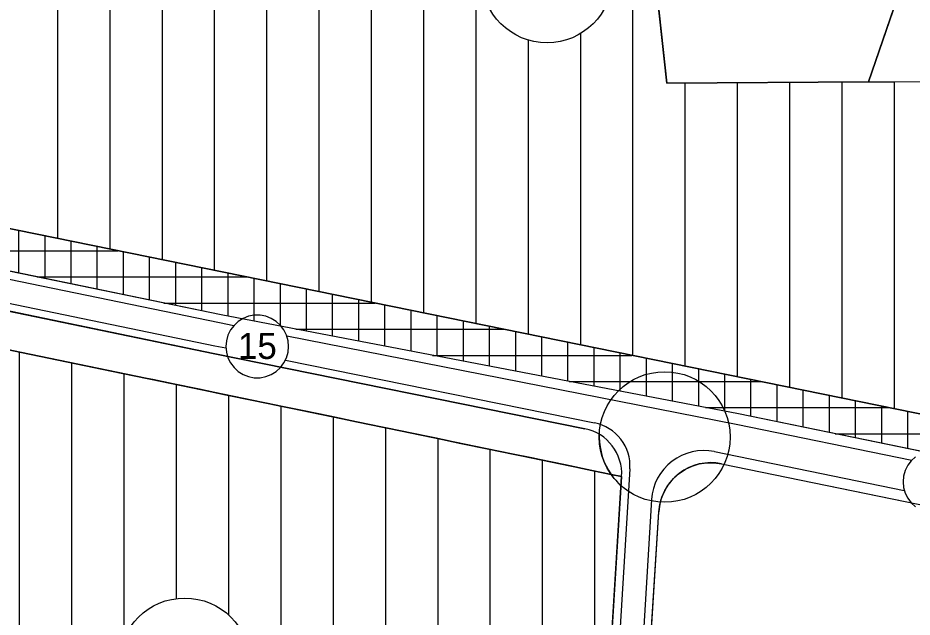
# Model space of a CAD drawing. Extents: x 427903 to 430077, y 4477233 to 4480385.
# Drawn here: x 428977.5 to 429319.5, y 4477464.3 to 4477693.6 of the extents above; entities that cross this region are included whole.
import ezdxf

# ---------------------------------------------------------------- set-up
doc = ezdxf.new("R2010")
doc.units = 0
for name, color, linetype in [('ADA', 7, 'Continuous'), ('ADAKENARI', 7, 'Continuous'), ('KALDIRIM', 7, 'Continuous'), ('KD_DAIRE', 7, 'Continuous'), ('KD_KAV_DA', 7, 'Continuous'), ('KD_YGEN', 7, 'Continuous'), ('PL_K_BHA', 7, 'Continuous'), ('PL_K_TALI_IS_MRK', 7, 'Continuous'), ('PL_KON_MEV_150', 7, 'Continuous'), ('PL_SAY_SPOR', 7, 'Continuous'), ('SM_DAIRE', 7, 'Continuous'), ('TR_AZYOGUNKONUT', 7, 'Continuous'), ('TR_TALIISMERK', 7, 'Continuous')]:
    doc.layers.add(name, color=color, linetype=linetype)

msp = doc.modelspace()

# ---------------------------------------------------------------- linework, layer by layer
at = {"layer": 'ADA'}
for p, q in [((429217.51, 4477743.44), (429225.77, 4477668.67)), ((429302.83, 4477669.13), (429323.01, 4477727.85)), ((429225.77, 4477668.67), (429302.83, 4477669.13)), ((429302.83, 4477669.13), (429349.51, 4477669.41))]:
    msp.add_line(p, q, dxfattribs=at)
at = {"layer": 'ADAKENARI'}
for p, q in [((429528.47, 4477500.12), (428912.77, 4477625.48)), ((429055.28, 4477579.93), (428907.79, 4477610.43)), ((428924.99, 4477591.56), (429052.27, 4477565.24)), ((429253.08, 4477542.08), (429055.28, 4477579.93)), ((428978.93, 4477565.57), (429208.41, 4477518.08)), ((429052.27, 4477565.24), (429194.39, 4477536.36)), ((429530.08, 4477485.18), (429253.08, 4477542.08)), ((429246.63, 4477522.99), (429411.9, 4477489.04)), ((429208.41, 4477518.08), (429198.53, 4477358.41)), ((429213.49, 4477357.28), (429222.61, 4477504.61))]:
    msp.add_line(p, q, dxfattribs=at)
for centre, radius, start, end in [((429190.9, 4477519.16), 17.55, 356.4594, 78.5144), ((429242.6, 4477503.38), 20.03, 78.3918, 176.4594)]:
    msp.add_arc(centre, radius, start, end, dxfattribs=at)
at = {"layer": 'KALDIRIM'}
for p, q in [((428907.19, 4477607.49), (429054.67, 4477577)), ((428925.59, 4477594.5), (429052.87, 4477568.18)), ((429054.67, 4477577), (429060.15, 4477575.92)), ((429080.33, 4477571.95), (429252.27, 4477538.17)), ((429052.87, 4477568.18), (429057.06, 4477567.33)), ((429079.88, 4477562.69), (429198.02, 4477538.69)), ((429252.27, 4477538.17), (429319.4, 4477524.38)), ((429243.88, 4477527.64), (429316.54, 4477512.72)), ((429211.6, 4477520.98), (429206.63, 4477440.76)), ((429219.89, 4477509.29), (429215.61, 4477440.13))]:
    msp.add_line(p, q, dxfattribs=at)
for centre, radius, start, end in [((429194.63, 4477522.03), 17, 356.4594, 78.5144), ((429239.85, 4477508.05), 20, 78.3918, 176.4594)]:
    msp.add_arc(centre, radius, start, end, dxfattribs=at)
at = {"layer": 'KD_DAIRE'}
for p, q in [((429063.7, 4477578.61), (429061.82, 4477577.44)), ((429063.7, 4477578.61), (429061.82, 4477577.44)), ((429065.77, 4477579.41), (429063.7, 4477578.61)), ((429065.77, 4477579.41), (429063.7, 4477578.61)), ((429067.94, 4477579.82), (429065.77, 4477579.41)), ((429067.94, 4477579.82), (429065.77, 4477579.41)), ((429070.16, 4477579.82), (429067.94, 4477579.82)), ((429070.16, 4477579.82), (429067.94, 4477579.82)), ((429072.33, 4477579.41), (429070.16, 4477579.82)), ((429072.33, 4477579.41), (429070.16, 4477579.82)), ((429074.4, 4477578.61), (429072.33, 4477579.41)), ((429074.4, 4477578.61), (429072.33, 4477579.41)), ((429076.28, 4477577.44), (429074.4, 4477578.61)), ((429076.28, 4477577.44), (429074.4, 4477578.61)), ((429060.18, 4477575.95), (429058.85, 4477574.19)), ((429060.18, 4477575.95), (429058.85, 4477574.19)), ((429061.82, 4477577.44), (429060.18, 4477575.95)), ((429061.82, 4477577.44), (429060.18, 4477575.95)), ((429077.92, 4477575.95), (429076.28, 4477577.44)), ((429077.92, 4477575.95), (429076.28, 4477577.44)), ((429079.25, 4477574.19), (429077.92, 4477575.95)), ((429079.25, 4477574.19), (429077.92, 4477575.95)), ((429057.86, 4477572.2), (429057.25, 4477570.07)), ((429057.86, 4477572.2), (429057.25, 4477570.07)), ((429058.85, 4477574.19), (429057.86, 4477572.2)), ((429058.85, 4477574.19), (429057.86, 4477572.2)), ((429080.24, 4477572.2), (429079.25, 4477574.19)), ((429080.24, 4477572.2), (429079.25, 4477574.19)), ((429080.84, 4477570.07), (429080.24, 4477572.2)), ((429080.84, 4477570.07), (429080.24, 4477572.2)), ((429057.25, 4477570.07), (429057.05, 4477567.87)), ((429057.25, 4477570.07), (429057.05, 4477567.87)), ((429081.05, 4477567.87), (429080.84, 4477570.07)), ((429081.05, 4477567.87), (429080.84, 4477570.07)), ((429057.05, 4477567.87), (429057.25, 4477565.66)), ((429057.05, 4477567.87), (429057.25, 4477565.66)), ((429057.25, 4477565.66), (429057.86, 4477563.53)), ((429057.25, 4477565.66), (429057.86, 4477563.53)), ((429080.24, 4477563.53), (429080.84, 4477565.66)), ((429080.24, 4477563.53), (429080.84, 4477565.66)), ((429080.84, 4477565.66), (429081.05, 4477567.87)), ((429080.84, 4477565.66), (429081.05, 4477567.87)), ((429081.05, 4477567.87), (429081.05, 4477567.87)), ((429081.05, 4477567.87), (429081.05, 4477567.87)), ((429057.86, 4477563.53), (429058.85, 4477561.55)), ((429057.86, 4477563.53), (429058.85, 4477561.55)), ((429058.85, 4477561.55), (429060.18, 4477559.78)), ((429058.85, 4477561.55), (429060.18, 4477559.78)), ((429077.92, 4477559.78), (429079.25, 4477561.55)), ((429077.92, 4477559.78), (429079.25, 4477561.55)), ((429079.25, 4477561.55), (429080.24, 4477563.53)), ((429079.25, 4477561.55), (429080.24, 4477563.53)), ((429060.18, 4477559.78), (429061.82, 4477558.29)), ((429060.18, 4477559.78), (429061.82, 4477558.29)), ((429061.82, 4477558.29), (429063.7, 4477557.13)), ((429061.82, 4477558.29), (429063.7, 4477557.13)), ((429074.4, 4477557.13), (429076.28, 4477558.29)), ((429074.4, 4477557.13), (429076.28, 4477558.29)), ((429076.28, 4477558.29), (429077.92, 4477559.78)), ((429076.28, 4477558.29), (429077.92, 4477559.78)), ((429063.7, 4477557.13), (429065.77, 4477556.33)), ((429063.7, 4477557.13), (429065.77, 4477556.33)), ((429065.77, 4477556.33), (429067.94, 4477555.92)), ((429065.77, 4477556.33), (429067.94, 4477555.92)), ((429067.94, 4477555.92), (429070.16, 4477555.92)), ((429067.94, 4477555.92), (429070.16, 4477555.92)), ((429070.16, 4477555.92), (429072.33, 4477556.33)), ((429070.16, 4477555.92), (429072.33, 4477556.33)), ((429072.33, 4477556.33), (429074.4, 4477557.13)), ((429072.33, 4477556.33), (429074.4, 4477557.13)), ((429319.19, 4477524.15), (429317.86, 4477522.38)), ((429319.19, 4477524.15), (429317.86, 4477522.38)), ((429320.83, 4477525.64), (429319.19, 4477524.15)), ((429320.83, 4477525.64), (429319.19, 4477524.15)), ((429316.87, 4477520.4), (429316.26, 4477518.27)), ((429316.87, 4477520.4), (429316.26, 4477518.27)), ((429317.86, 4477522.38), (429316.87, 4477520.4)), ((429317.86, 4477522.38), (429316.87, 4477520.4)), ((429316.26, 4477518.27), (429316.06, 4477516.06)), ((429316.26, 4477518.27), (429316.06, 4477516.06)), ((429316.06, 4477516.06), (429316.26, 4477513.86)), ((429316.06, 4477516.06), (429316.26, 4477513.86)), ((429316.26, 4477513.86), (429316.87, 4477511.73)), ((429316.26, 4477513.86), (429316.87, 4477511.73)), ((429316.87, 4477511.73), (429317.86, 4477509.75)), ((429316.87, 4477511.73), (429317.86, 4477509.75)), ((429317.86, 4477509.75), (429319.19, 4477507.98)), ((429317.86, 4477509.75), (429319.19, 4477507.98)), ((429319.19, 4477507.98), (429320.83, 4477506.49)), ((429319.19, 4477507.98), (429320.83, 4477506.49))]:
    msp.add_line(p, q, dxfattribs=at)
at = {"layer": 'KD_KAV_DA'}
msp.add_circle((429224.89, 4477533.22), 25, dxfattribs=at)
at = {"layer": 'PL_K_BHA'}
msp.add_lwpolyline([(429325.91, 4477853.36), (429323.01, 4477727.85), (429302.83, 4477669.13), (429225.77, 4477668.67), (429217.51, 4477743.44), (429182.19, 4477742.53), (429185.4, 4477776.47), (429130.82, 4477785.19), (429146.75, 4477845.66), (429150.95, 4477861.61), (429260.07, 4477868.35), (429268.61, 4477868.97), (429281.61, 4477869.09), (429292.6, 4477869.49), (429326.26, 4477868.29)], close=True, dxfattribs=at)
at = {"layer": 'PL_K_TALI_IS_MRK'}
for points in [[(428912.77, 4477625.48), (429528.47, 4477500.12)], [(429530.08, 4477485.18), (429253.08, 4477542.08), (429055.28, 4477579.93), (428907.79, 4477610.43)], [(429194.39, 4477536.36), (429052.27, 4477565.24), (428945.43, 4477587.33), (428942.16, 4477573.18), (428978.93, 4477565.57), (429016.97, 4477557.7)], [(429016.97, 4477557.7), (429026.97, 4477555.63), (429029.11, 4477555.19), (429036.97, 4477553.56), (429046.97, 4477551.49), (429056.97, 4477549.42), (429066.97, 4477547.35), (429076.97, 4477545.28), (429077.42, 4477545.19), (429086.97, 4477543.21), (429096.97, 4477541.14), (429106.97, 4477539.07), (429116.97, 4477537), (429125.74, 4477535.19), (429126.97, 4477534.93), (429136.97, 4477532.86), (429146.97, 4477530.79), (429156.97, 4477528.73), (429166.97, 4477526.66), (429174.06, 4477525.19), (429176.97, 4477524.59), (429186.97, 4477522.52), (429196.97, 4477520.45), (429204.39, 4477518.91), (429208.41, 4477518.08)]]:
    msp.add_lwpolyline(points, dxfattribs=at)
msp.add_arc((429190.9, 4477519.16), 17.55, 356.4594, 78.5144, dxfattribs=at)
at = {"layer": 'PL_KON_MEV_150'}
msp.add_lwpolyline([(429217.51, 4477743.44), (429225.77, 4477668.67), (429302.83, 4477669.13), (429349.51, 4477669.41), (429349.16, 4477727.85), (429323.01, 4477727.85), (429325.91, 4477853.36), (429488.36, 4477840.99), (429552.87, 4477514.62), (429528.47, 4477500.12), (428912.77, 4477625.48), (428938.14, 4477835.78), (429146.75, 4477845.66), (429130.82, 4477785.19), (429185.4, 4477776.47), (429182.19, 4477742.53)], close=True, dxfattribs=at)
msp.add_lwpolyline([(429198.53, 4477358.41), (429208.41, 4477518.08), (429204.39, 4477518.91), (429196.97, 4477520.45), (429186.97, 4477522.52), (429176.97, 4477524.59), (429174.06, 4477525.19), (429166.97, 4477526.66), (429156.97, 4477528.73), (429146.97, 4477530.79), (429136.97, 4477532.86), (429126.97, 4477534.93), (429125.74, 4477535.19), (429116.97, 4477537), (429106.97, 4477539.07), (429096.97, 4477541.14), (429086.97, 4477543.21), (429077.42, 4477545.19), (429076.97, 4477545.28), (429066.97, 4477547.35), (429056.97, 4477549.42), (429046.97, 4477551.49), (429036.97, 4477553.56), (429029.11, 4477555.19), (429026.97, 4477555.63), (429016.97, 4477557.7), (428978.93, 4477565.57), (428942.16, 4477573.18)], dxfattribs=at)
at = {"layer": 'PL_SAY_SPOR'}
for points in [[(429332.77, 4477669.31), (429349.51, 4477669.41), (429349.16, 4477727.85), (429332.77, 4477727.85), (429323.01, 4477727.85), (429302.83, 4477669.13), (429312.77, 4477669.19), (429332.77, 4477669.31)], [(429325.84, 4477331.6), (429212.33, 4477344.27), (429213.49, 4477357.28), (429222.61, 4477504.61), (429222.99, 4477507.44), (429223.76, 4477510.19), (429224.92, 4477512.8), (429226.44, 4477515.21), (429228.29, 4477517.39), (429230.43, 4477519.28), (429232.81, 4477520.85), (429235.39, 4477522.06), (429238.12, 4477522.9), (429240.94, 4477523.33), (429243.8, 4477523.37), (429246.63, 4477522.99), (429411.9, 4477489.04)]]:
    msp.add_lwpolyline(points, dxfattribs=at)
at = {"layer": 'SM_DAIRE'}
for centre in [(429179.89, 4477709.1), (429041.35, 4477446.59)]:
    msp.add_circle(centre, 25, dxfattribs=at)
at = {"layer": 'TR_AZYOGUNKONUT'}
for p, q in [((429072.77, 4477592.9), (429072.77, 4477842.16)), ((429092.77, 4477588.83), (429092.77, 4477843.1)), ((429112.77, 4477584.76), (429112.77, 4477844.05)), ((428992.77, 4477609.19), (428992.77, 4477838.37)), ((429012.77, 4477605.12), (429012.77, 4477839.31)), ((429032.77, 4477601.05), (429032.77, 4477840.26)), ((429052.77, 4477596.97), (429052.77, 4477841.21)), ((429132.77, 4477580.69), (429132.77, 4477784.87)), ((429152.77, 4477576.61), (429152.77, 4477781.68)), ((429212.77, 4477564.4), (429212.77, 4477743.32)), ((429172.77, 4477572.54), (429172.77, 4477685.13)), ((429192.77, 4477568.47), (429192.77, 4477687.67)), ((429232.77, 4477560.33), (429232.77, 4477668.72)), ((429252.77, 4477556.25), (429252.77, 4477668.83)), ((429272.77, 4477552.18), (429272.77, 4477668.95)), ((429292.77, 4477548.11), (429292.77, 4477669.07)), ((429312.77, 4477544.04), (429312.77, 4477669.19)), ((428978.2, 4477461.06), (428978.2, 4477565.72)), ((428998.2, 4477347.08), (428998.2, 4477561.58)), ((429018.2, 4477456.05), (429018.2, 4477557.44)), ((429038.2, 4477471.4), (429038.2, 4477553.31)), ((429058.2, 4477465.06), (429058.2, 4477549.17)), ((429078.2, 4477339.77), (429078.2, 4477545.03)), ((429098.2, 4477337.94), (429098.2, 4477540.89)), ((429118.2, 4477336.11), (429118.2, 4477536.75)), ((429138.2, 4477334.28), (429138.2, 4477532.61)), ((429158.2, 4477464.4), (429158.2, 4477528.47)), ((429178.2, 4477460.93), (429178.2, 4477524.33)), ((429198.2, 4477457.45), (429198.2, 4477520.19)), ((429158.2, 4477332.45), (429158.2, 4477464.4))]:
    msp.add_line(p, q, dxfattribs=at)
for points in [[(429204.39, 4477518.91), (428978.93, 4477565.57), (428942.16, 4477573.18), (428939.78, 4477562.84), (428951.55, 4477560.51), (428949.08, 4477551.4), (428944.47, 4477534.41), (428920.67, 4477537.5), (428893.84, 4477540.99), (428893.57, 4477524.11), (428892.66, 4477466.82)], [(429204.39, 4477518.91), (429196.97, 4477520.45), (429186.97, 4477522.52), (429176.97, 4477524.59), (429174.06, 4477525.19), (429166.97, 4477526.66), (429156.97, 4477528.73), (429146.97, 4477530.79), (429136.97, 4477532.86), (429126.97, 4477534.93), (429125.74, 4477535.19), (429116.97, 4477537), (429106.97, 4477539.07), (429096.97, 4477541.14), (429086.97, 4477543.21), (429077.42, 4477545.19), (429076.97, 4477545.28), (429066.97, 4477547.35), (429056.97, 4477549.42), (429046.97, 4477551.49), (429036.97, 4477553.56), (429029.11, 4477555.19), (429026.97, 4477555.63), (429016.97, 4477557.7), (428978.93, 4477565.57)], [(429204.39, 4477518.91), (429196.97, 4477520.45), (429186.97, 4477522.52), (429176.97, 4477524.59), (429174.06, 4477525.19), (429166.97, 4477526.66), (429156.97, 4477528.73), (429146.97, 4477530.79), (429136.97, 4477532.86), (429126.97, 4477534.93), (429125.74, 4477535.19), (429116.97, 4477537), (429106.97, 4477539.07), (429096.97, 4477541.14), (429086.97, 4477543.21), (429077.42, 4477545.19), (429076.97, 4477545.28), (429066.97, 4477547.35), (429056.97, 4477549.42), (429046.97, 4477551.49), (429036.97, 4477553.56), (429029.11, 4477555.19), (429026.97, 4477555.63), (429016.97, 4477557.7)], [(429203.53, 4477439.18), (429208.2, 4477514.61)]]:
    msp.add_lwpolyline(points, dxfattribs=at)
for start, end in [(177.82, 180), (180, 214.9214), (214.9214, 228.1118), (214.9214, 228.1118), (214.9214, 228.1118)]:
    msp.add_arc((429224.89, 4477533.22), 25, start, end, dxfattribs=at)
at = {"layer": 'TR_TALIISMERK'}
for p, q in [((428977.9, 4477595.93), (428977.9, 4477612.22)), ((428987.9, 4477593.87), (428987.9, 4477610.18)), ((428997.9, 4477591.8), (428997.9, 4477608.15)), ((429007.9, 4477589.73), (429007.9, 4477606.11)), ((428936.58, 4477604.48), (429015.91, 4477604.48)), ((429017.9, 4477587.66), (429017.9, 4477604.07)), ((429027.9, 4477585.59), (429027.9, 4477602.04)), ((429037.9, 4477583.53), (429037.9, 4477600)), ((429047.9, 4477581.46), (429047.9, 4477597.97)), ((429057.9, 4477579.43), (429057.9, 4477595.93)), ((428984.93, 4477594.48), (429065.02, 4477594.48)), ((429067.9, 4477577.52), (429067.9, 4477593.89)), ((429077.9, 4477575.6), (429077.9, 4477591.86)), ((429087.9, 4477573.69), (429087.9, 4477589.82)), ((429097.9, 4477571.78), (429097.9, 4477587.79)), ((429107.9, 4477569.86), (429107.9, 4477585.75)), ((429033.29, 4477584.48), (429114.14, 4477584.48)), ((429117.9, 4477567.95), (429117.9, 4477583.71)), ((429127.9, 4477566.04), (429127.9, 4477581.68)), ((429137.9, 4477564.12), (429137.9, 4477579.64)), ((429147.9, 4477562.21), (429147.9, 4477577.61)), ((429157.9, 4477560.3), (429157.9, 4477575.57)), ((429083.78, 4477574.48), (429163.25, 4477574.48)), ((429167.9, 4477558.38), (429167.9, 4477573.53)), ((429177.9, 4477556.47), (429177.9, 4477571.5)), ((429187.9, 4477554.56), (429187.9, 4477569.46)), ((429197.9, 4477552.64), (429197.9, 4477567.42)), ((429207.9, 4477550.73), (429207.9, 4477565.39)), ((429136.04, 4477564.48), (429212.37, 4477564.48)), ((429217.9, 4477548.81), (429217.9, 4477563.35)), ((429227.9, 4477546.9), (429227.9, 4477561.32)), ((429237.9, 4477544.99), (429237.9, 4477559.28)), ((429188.3, 4477554.48), (429261.48, 4477554.48)), ((429247.9, 4477543.07), (429247.9, 4477557.24)), ((429257.9, 4477541.09), (429257.9, 4477555.21)), ((429267.9, 4477539.04), (429267.9, 4477553.17)), ((429277.9, 4477536.98), (429277.9, 4477551.14)), ((429287.9, 4477534.93), (429287.9, 4477549.1)), ((429240.56, 4477544.48), (429310.6, 4477544.48)), ((429297.9, 4477532.88), (429297.9, 4477547.06)), ((429307.9, 4477530.82), (429307.9, 4477545.03)), ((429317.9, 4477528.77), (429317.9, 4477542.99)), ((429290.09, 4477534.48), (429359.71, 4477534.48))]:
    msp.add_line(p, q, dxfattribs=at)
for points in [[(429194.39, 4477536.36), (429052.27, 4477565.24), (428945.43, 4477587.33), (428942.16, 4477573.18), (428978.93, 4477565.57), (429016.97, 4477557.7)], [(429016.97, 4477557.7), (429026.97, 4477555.63), (429029.11, 4477555.19), (429036.97, 4477553.56), (429046.97, 4477551.49), (429056.97, 4477549.42), (429066.97, 4477547.35), (429076.97, 4477545.28), (429077.42, 4477545.19), (429086.97, 4477543.21), (429096.97, 4477541.14), (429106.97, 4477539.07), (429116.97, 4477537), (429125.74, 4477535.19), (429126.97, 4477534.93), (429136.97, 4477532.86), (429146.97, 4477530.79), (429156.97, 4477528.73), (429166.97, 4477526.66), (429174.06, 4477525.19), (429176.97, 4477524.59), (429186.97, 4477522.52), (429196.97, 4477520.45), (429204.39, 4477518.91), (429208.41, 4477518.08)]]:
    msp.add_lwpolyline(points, dxfattribs=at)
msp.add_arc((429190.9, 4477519.16), 17.55, 356.4594, 78.5144, dxfattribs=at)

# ---------------------------------------------------------------- texts
at = {"layer": 'KD_YGEN'}
msp.add_text('15', height=10, dxfattribs=at).set_placement((429061.67, 4477563.09))

doc.saveas('drawing.dxf')
